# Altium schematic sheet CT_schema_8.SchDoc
size 146 x 119 mm
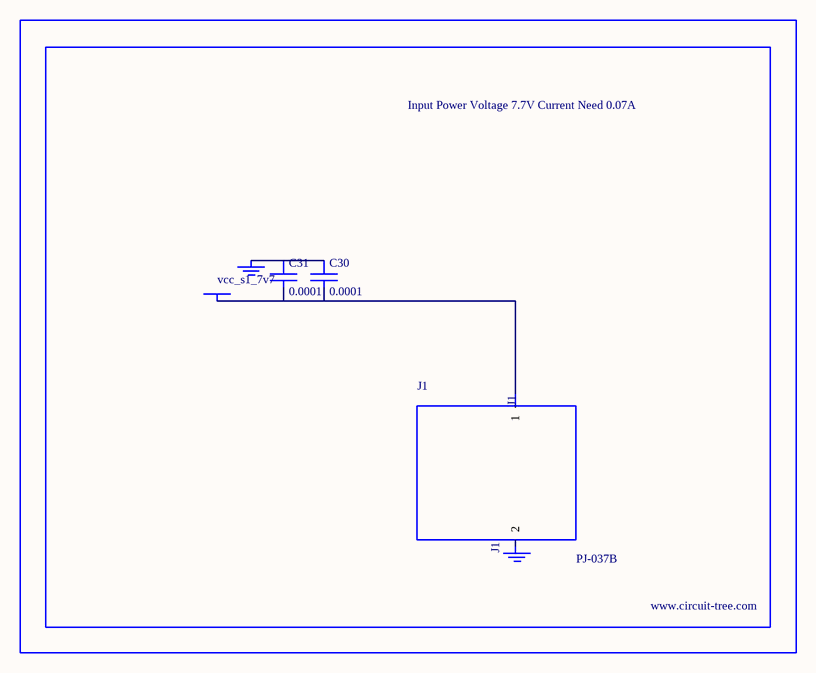
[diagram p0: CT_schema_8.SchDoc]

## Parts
BORDER7  (no value)
C30  0.0001  [EXV-9H]
C31  0.0001  [EXV-9H]
GND_INSTANCE_7_0  (no value)
GND_INSTANCE_7_1  (no value)
J1  PJ-037B  [PJ-037B_PACKAGE]
POWER_INSTANCE_7_0  vcc_s1_7v7

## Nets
NetC30_1: C30.1 C31.1 GND_INSTANCE_7_0.0(GND)
NetC30_2: C30.2 C31.2 J1.1 POWER_INSTANCE_7_0.0(PWR)

Not connected (* = marked no-connect by the designer): GND_INSTANCE_7_1 0(GND); J1 2

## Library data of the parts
BORDER7 = BORDER_PAGE7
C30 C31 = EDK107M035A9HAA
GND_INSTANCE_7_0 GND_INSTANCE_7_1 = GND
POWER_INSTANCE_7_0 = PWR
